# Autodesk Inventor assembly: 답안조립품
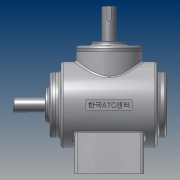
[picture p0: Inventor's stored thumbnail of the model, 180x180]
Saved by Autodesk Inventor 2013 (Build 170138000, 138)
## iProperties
Created: 2015-01
Part Number: 답안조립품
Document SubType Name: Weldment
Designer: Administrator
Weld Material: Welded Aluminum-6061
Author: Administrator
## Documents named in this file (15)
- C:\Users\Administrator\Desktop\450106V1015\답안조립품.iam
- C:\Users\Administrator\Desktop\450106V1015\답안본체.ipt
- C:\Users\Administrator\Desktop\450106V1015\450106V1015\M4.ipt
- C:\Users\Administrator\Desktop\450106V1015\450106V1015\메인 베벨기어.ipt
- C:\Users\Administrator\Desktop\450106V1015\450106V1015\메인 축.ipt
- 메인 축.ipt
- C:\Users\Administrator\Desktop\450106V1015\450106V1015\베어링 6203.ipt
- C:\Users\Administrator\Desktop\450106V1015\450106V1015\서브 베벨기어.ipt
- C:\Users\Administrator\Desktop\450106V1015\450106V1015\서브 축.ipt
- 서브 축.ipt
- C:\Users\Administrator\Desktop\450106V1015\450106V1015\오일실.ipt
- C:\Users\Administrator\Desktop\450106V1015\450106V1015\커버.ipt
- C:\Users\Administrator\Desktop\450106V1015\450106V1015\커버2.ipt
- C:\Users\Administrator\Desktop\450106V1015\450106V1015\키 4x4.ipt
- C:\Users\Administrator\Desktop\450106V1015\450106V1015\키 5x5.ipt
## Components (12 placed, 1 different names)
1. M4:1 — 각도:7
2. M4:2
3. M4:3
4. M4:4
5. M4:5 — 각도:8
6. M4:7
7. M4:8
8. M4:9
9. M4:6 — 각도:9
10. M4:10
11. M4:11
12. M4:12
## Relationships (3: Angle 3)
- 각도:7 [Angle]: M4:1
- 각도:8 [Angle]: M4:5
- 각도:9 [Angle]: M4:6
